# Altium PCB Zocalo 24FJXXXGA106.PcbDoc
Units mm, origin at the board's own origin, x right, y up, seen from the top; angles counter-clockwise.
Board outline 80.82 x 80.01 mm, 2 copper layers (TopLayer, BottomLayer); 8 components, 106 nets, 200 pads, 93 vias.
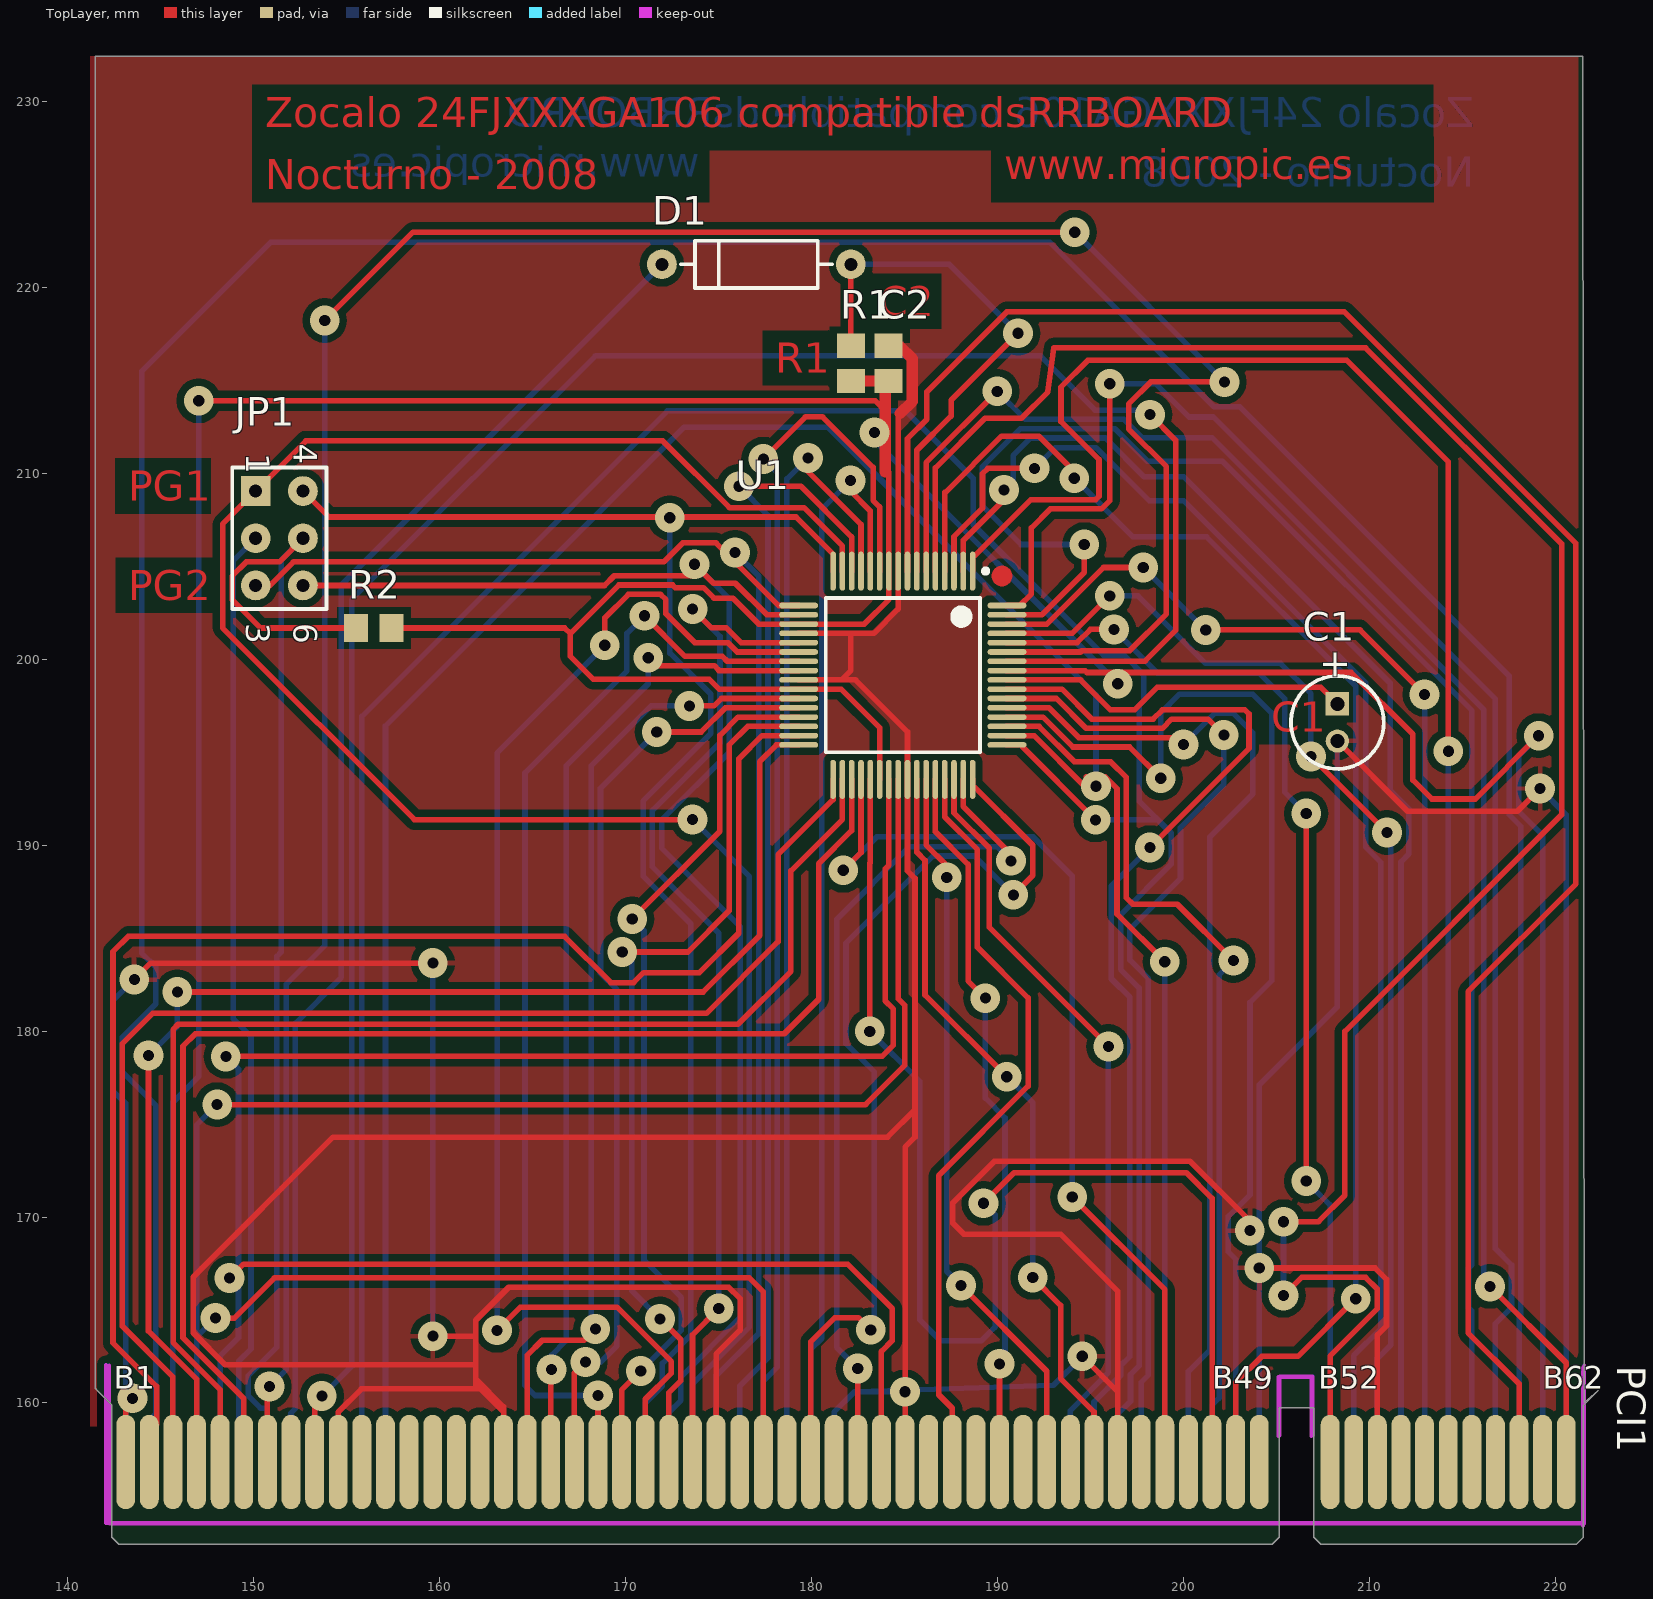
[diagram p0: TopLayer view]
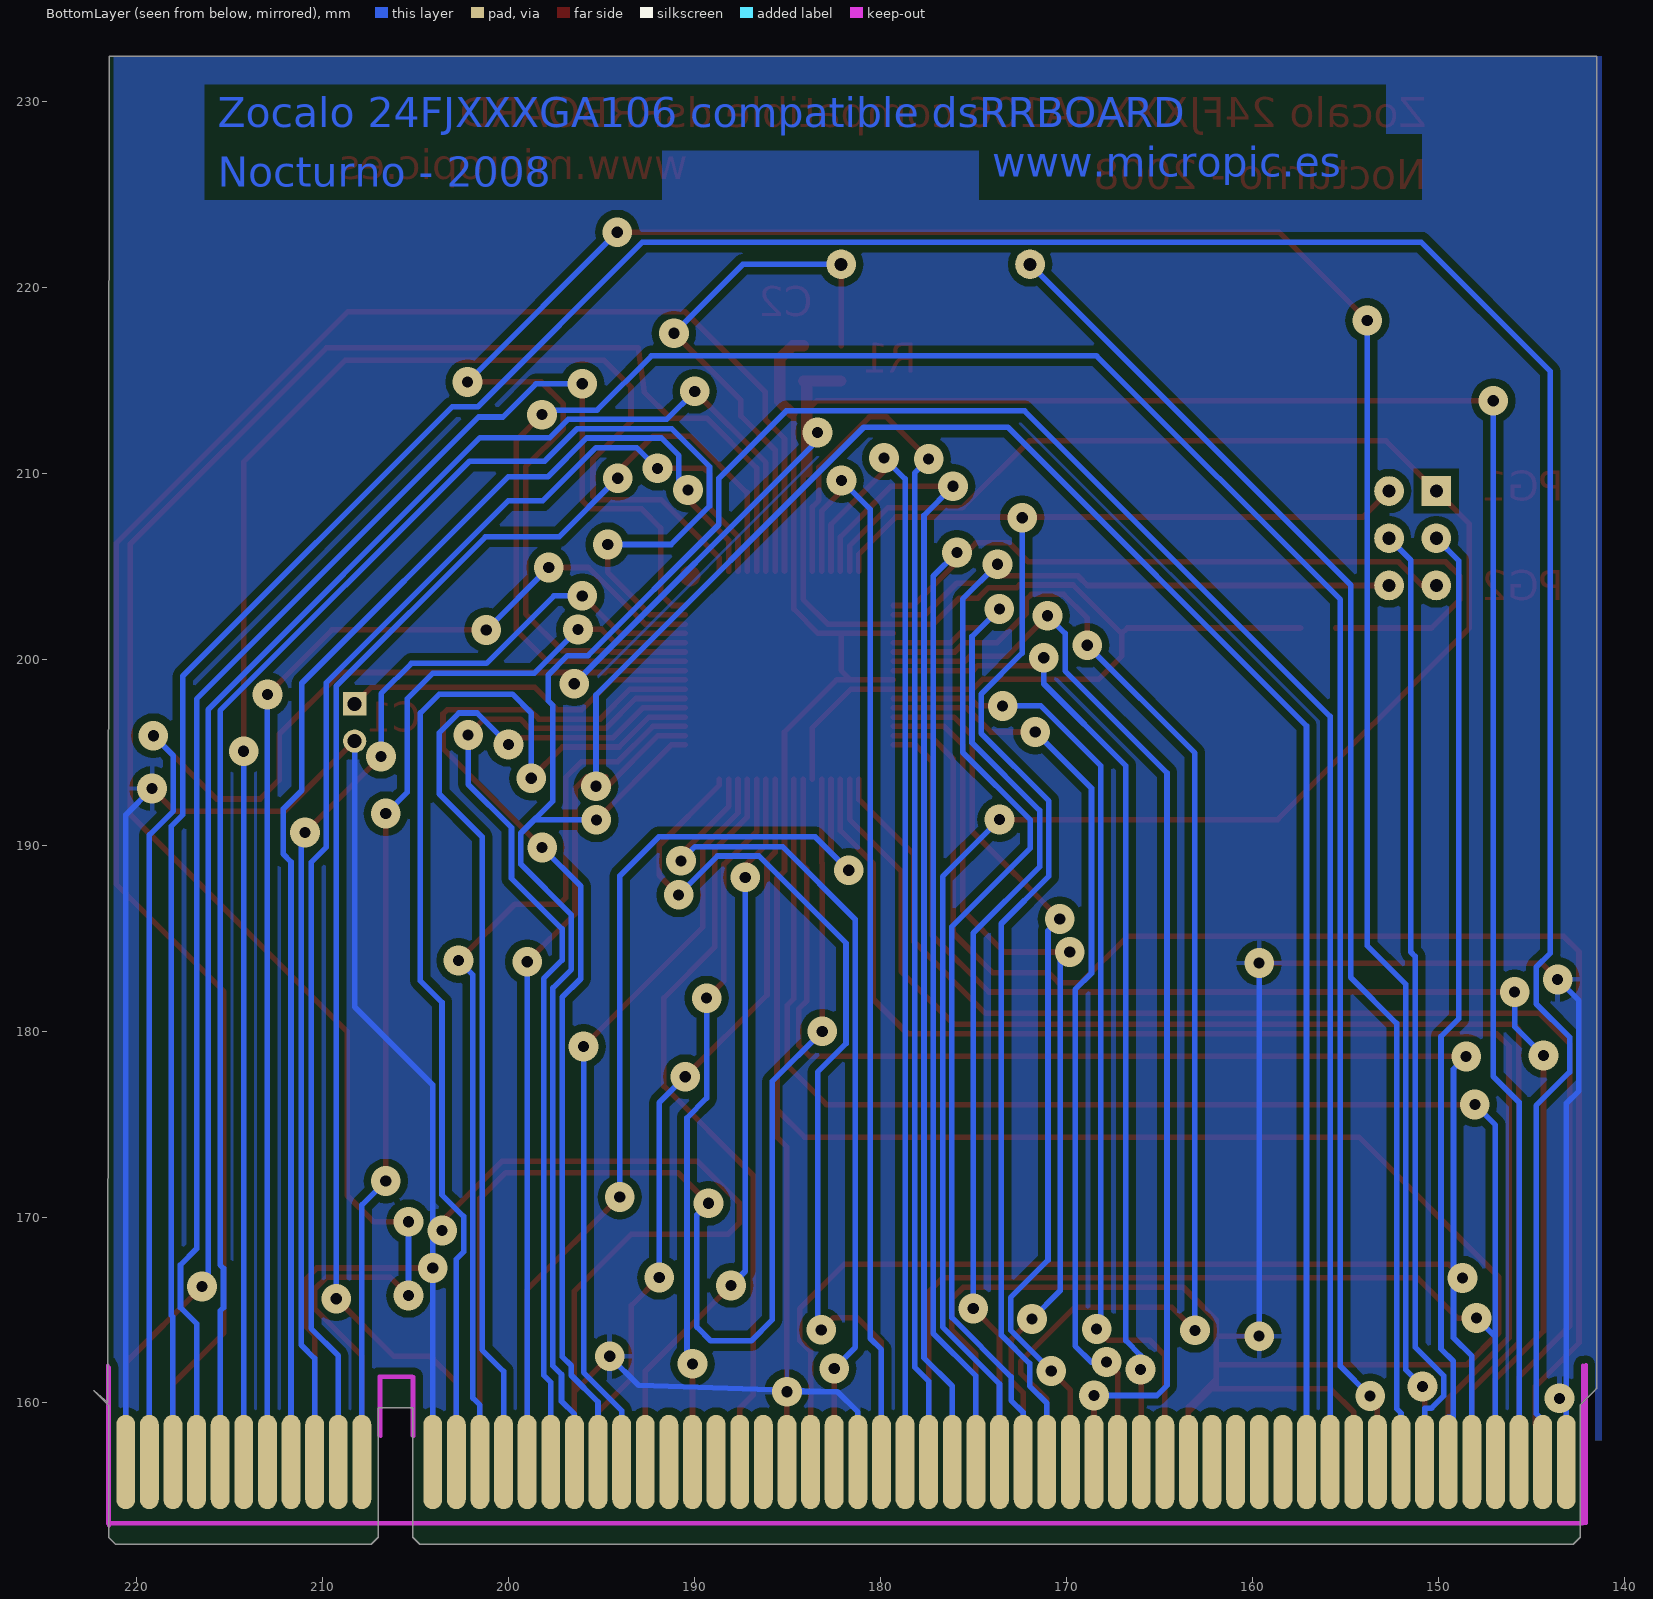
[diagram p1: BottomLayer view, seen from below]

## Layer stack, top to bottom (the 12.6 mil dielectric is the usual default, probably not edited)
TopLayer: signal copper 0.0356
Dielectric: core 0.32, FR-4, Dk 4.8
BottomLayer: signal copper 0.0356

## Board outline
141.478,160.782 142.367,159.893 142.367,152.781 142.748,152.4 204.775,152.4 205.156,152.781 205.156,159.741 207.01,159.741 207.01,152.781 207.391,152.4 221.132,152.4 221.513,152.781 221.513,159.868 222.301,160.655 221.553,160.02 221.488,232.41 141.478,232.41

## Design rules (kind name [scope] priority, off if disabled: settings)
Clearance [All] p1: gap=0.2
ComponentClearance [All] p1: gap=0.254 collisioncheckmode=0 verticalgap=0.254
PasteMaskExpansion PasteMaskExpansion_1 [InComponent('P1')] p1: expansion=-2.54
PasteMaskExpansion [All] p2: expansion=0
PlaneClearance [All] p1: clearance=0.254
PolygonConnect [All] p1: connectstyle=Relief reliefconductorwidth=0.254 reliefentries=4 polygonreliefangle="90 Angle"
RoutingVias [All] p1: holewidth=0.6 width=1.6 viastyle="Through Hole" minholewidth=0.6 minwidth=1.6 maxholewidth=0.6 maxwidth=1.6
SolderMaskExpansion [All] p1: expansion=0.051
TestPointUsage [All] p1: valid=0 allowmultiple=FALSE
Testpoint [All] p1: side=7 testpointundercomponent=TRUE minsize=1.016 maxsize=2.54 preferedsize=1.524 minholesize=0.508 maxholesize=1.016 preferedholesize=0.813 testpointgrid=0.025 style=1001 order=0123456789
Width [All] p1: maxlimit=0.6 minlimit=0.254 preferedwidth=0.4 toplayer_prefwidth=0.3 bottomlayer_prefwidth=0.3 minimp=50.000000 maximp=50.000000 favimp=50.000000
16 further rules are at their usual default settings.

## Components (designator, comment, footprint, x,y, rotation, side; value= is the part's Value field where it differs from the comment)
C1 "10uF" B 208.28,196.596 r270 top
C2 "100nF" 2012[0805] 184.15,215.9 r270 top
D1 "BAT85" DIODE-0.4 177.038,221.234 r180 top
JP1 "Header 3X2A" HDR2X3_CEN 150.114,209.042 r270 top
PCI1 "Conector PCI Macho" PCI_MACHO 170.688,162.052 r0 top
R1 "Res1" 2012[0805] 182.118,215.9 r270 top
R2 "220" 2012[0805] 156.464,201.676 r0 top
U1 "24FJXXXGA106" TQFP64_M 184.912,199.136 r270 top

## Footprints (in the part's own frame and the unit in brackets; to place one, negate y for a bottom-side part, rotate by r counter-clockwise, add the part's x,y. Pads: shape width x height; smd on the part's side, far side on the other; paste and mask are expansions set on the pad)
2012[0805] [mm] "Chip Resistor; Body 2.0 x 1.3 mm (LxW typ)"
  rect 1.3x1.5 smd: 1(-0.95,0) 2(0.95,0)
B [mm] "Capacitor, Electrolytic, Radial; Body 5 x 6.8 mm (Dia.xH typ); Pin Spacing 2 mm (typ)"
  rect 1.25x1.25 hole 0.75: 1(-1,0)
  round 1.25 hole 0.75: 2(1,0)
  silkscreen extent -2.5,-2.5 2.5,2.5
DIODE-0.4 [mm] "Tunnel Diode - Dependent Source Model; 2 Leads"
  round 1.6 hole 0.7: 1(-5.08,0) 2(5.08,0)
  silkscreen extent -4.06,-1.27 4.06,1.27
HDR2X3_CEN [mm] "Connector; Header; 3x2 Position"
  rect 1.6x1.6 hole 0.7: 1(0,0)
  round 1.6 hole 0.7: 2(2.54,0) 3(5.08,0) 4(0,2.54) 5(2.54,2.54) 6(5.08,2.54)
  silkscreen extent -1.27,-1.27 6.35,3.81
PCI_MACHO [mil] "Conector PCI Macho"
  oval 40x200 smd far side: A1(-1085.31,-205.75) A2(-1035.31,-205.75) A3(-985.31,-205.75) A4(-935.31,-205.75) A5(-885.31,-205.75) A6(-835.31,-205.75) A7(-785.31,-205.75) A8(-735.31,-205.75) A9(-685.31,-205.75) A10(-635.31,-205.75) A11(-585.31,-205.75) A12(-535.31,-205.75) A13(-485.31,-205.75) A14(-435.31,-205.75) A15(-385.31,-205.75) A16(-335.31,-205.75) A17(-285.31,-205.75) A18(-235.31,-205.75) A19(-185.31,-205.75) A20(-135.31,-205.75) A21(-85.31,-205.75) A22(-35.31,-205.75) A23(14.69,-205.75) A24(64.69,-205.75) A25(114.69,-205.75) A26(164.69,-205.75) A27(214.69,-205.75) A28(264.69,-205.75) A29(314.69,-205.75) A30(364.69,-205.75) A31(414.69,-205.75) A32(464.69,-205.75) A33(514.69,-205.75) A34(564.69,-205.75) A35(614.69,-205.75) A36(664.69,-205.75) A37(714.69,-205.75) A38(764.69,-205.75) A39(814.69,-205.75) A40(864.69,-205.75) A41(914.69,-205.75) A42(964.69,-205.75) A43(1014.69,-205.75) A44(1064.69,-205.75) A45(1114.69,-205.75) A46(1164.69,-205.75) A47(1214.69,-205.75) A48(1264.69,-205.75) A49(1314.69,-205.75) A50(1464.69,-205.75) A51(1514.69,-205.75) A52(1564.69,-205.75) A53(1614.69,-205.75) A54(1664.69,-205.75) A55(1714.69,-205.75) A56(1764.69,-205.75) A57(1814.69,-205.75) A58(1864.69,-205.75) A59(1914.69,-205.75) A60(1964.69,-205.75)
  oval 40x200 smd: B1(-1085.31,-205.75) B2(-1035.31,-205.75) B3(-985.31,-205.75) B4(-935.31,-205.75) B5(-885.31,-205.75) B6(-835.31,-205.75) B7(-785.31,-205.75) B8(-735.31,-205.75) B9(-685.31,-205.75) B10(-635.31,-205.75) B11(-585.31,-205.75) B12(-535.31,-205.75) B13(-485.31,-205.75) B14(-435.31,-205.75) B15(-385.31,-205.75) B16(-335.31,-205.75) B17(-285.31,-205.75) B18(-235.31,-205.75) B19(-185.31,-205.75) B20(-135.31,-205.75) B21(-85.31,-205.75) B22(-35.31,-205.75) B23(14.69,-205.75) B24(64.69,-205.75) B25(114.69,-205.75) B26(164.69,-205.75) B27(214.69,-205.75) B28(264.69,-205.75) B29(314.69,-205.75) B30(364.69,-205.75) B31(414.69,-205.75) B32(464.69,-205.75) B33(514.69,-205.75) B34(564.69,-205.75) B35(614.69,-205.75) B36(664.69,-205.75) B37(714.69,-205.75) B38(764.69,-205.75) B39(814.69,-205.75) B40(864.69,-205.75) B41(914.69,-205.75) B42(964.69,-205.75) B43(1014.69,-205.75) B44(1064.69,-205.75) B45(1114.69,-205.75) B46(1164.69,-205.75) B47(1214.69,-205.75) B48(1264.69,-205.75) B49(1314.69,-205.75) B50(1464.69,-205.75) B51(1514.69,-205.75) B52(1564.69,-205.75) B53(1614.69,-205.75) B54(1664.69,-205.75) B55(1714.69,-205.75) B56(1764.69,-205.75) B57(1814.69,-205.75) B58(1864.69,-205.75) B59(1914.69,-205.75) B60(1964.69,-205.75)
  KeepOutLayer lines w8: -1120.31,-0.75 -1120.31,-335.75 1998.63,-335.75 ; 1354.69,-150.75 1354.69,-25.75 1424.69,-25.75 1424.69,-150.75 ; 2002.57,-335.75 2002.57,-0.75
TQFP64_M [mm] "Thin QFP, 64-Leads, Body 10x10mm, Pitch 0.5mm, IPC Low Density"
  oval 2.1x0.3 smd: 1(-5.6,3.75) 2(-5.6,3.25) 3(-5.6,2.75) 4(-5.6,2.25) 5(-5.6,1.75) 6(-5.6,1.25) 7(-5.6,0.75) 8(-5.6,0.25) 9(-5.6,-0.25) 10(-5.6,-0.75) 11(-5.6,-1.25) 12(-5.6,-1.75) 13(-5.6,-2.25) 14(-5.6,-2.75) 15(-5.6,-3.25) 16(-5.6,-3.75) 33(5.6,-3.75) 34(5.6,-3.25) 35(5.6,-2.75) 36(5.6,-2.25) 37(5.6,-1.75) 38(5.6,-1.25) 39(5.6,-0.75) 40(5.6,-0.25) 41(5.6,0.25) 42(5.6,0.75) 43(5.6,1.25) 44(5.6,1.75) 45(5.6,2.25) 46(5.6,2.75) 47(5.6,3.25) 48(5.6,3.75)
  oval 0.3x2.1 smd: 17(-3.75,-5.6) 18(-3.25,-5.6) 19(-2.75,-5.6) 20(-2.25,-5.6) 21(-1.75,-5.6) 22(-1.25,-5.6) 23(-0.75,-5.6) 24(-0.25,-5.6) 25(0.25,-5.6) 26(0.75,-5.6) 27(1.25,-5.6) 28(1.75,-5.6) 29(2.25,-5.6) 30(2.75,-5.6) 31(3.25,-5.6) 32(3.75,-5.6) 49(3.75,5.6) 50(3.25,5.6) 51(2.75,5.6) 52(2.25,5.6) 53(1.75,5.6) 54(1.25,5.6) 55(0.75,5.6) 56(0.25,5.6) 57(-0.25,5.6) 58(-0.75,5.6) 59(-1.25,5.6) 60(-1.75,5.6) 61(-2.25,5.6) 62(-2.75,5.6) 63(-3.25,5.6) 64(-3.75,5.6)
  silkscreen extent -5.72,-4.15 4.15,4.58, body extent -5,-5 5,5, height 1.6

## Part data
C1: library part "Cap Pol2", "Polarized Capacitor (Axial)"
C2: library part Cap, "Capacitor"
D1: library part "Diode 1N4148", "High Conductance Fast Diode"
JP1: "Header, 3-Pin, Dual row"
R1: "Resistor"
R2: library part Res1, "Resistor"

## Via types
v1: diameter 1.6, hole 0.6, TopLayer to BottomLayer, 93 vias

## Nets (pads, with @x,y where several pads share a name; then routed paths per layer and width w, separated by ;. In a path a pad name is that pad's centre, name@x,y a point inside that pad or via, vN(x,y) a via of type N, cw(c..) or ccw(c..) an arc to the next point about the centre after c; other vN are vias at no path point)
A0: PCI1.A14
A1: PCI1.A16
A2: PCI1.A18
A3: PCI1.A20
A4: PCI1.A21
A5: PCI1.A19
A6: PCI1.A17
A7: PCI1.A15
A9: PCI1.B15
A10: PCI1.B13
A12: PCI1.B11
A13: PCI1.B12
A14: PCI1.B14
A15: PCI1.B16
B0: JP1.4 PCI1.A23 U1.16 | length 86.1
  TopLayer w0.3: JP1.4 154.05,207.646 179.166,207.646 181.162,205.65 U1.16 ; v1(172.381,207.603) v1@172.381,207.646
  BottomLayer w0.3: PCI1.A23 171.061,159.998 171.982,160.919 171.982,162.128 173.506,163.652 173.506,185.769 170.943,188.332 170.943,192.373 174.581,196.011 174.581,198.12 172.381,200.321 v1(172.381,207.603)
B1: JP1.1 PCI1.A25 U1.15 | length 111.1
  TopLayer w0.3: v1(173.601,191.371) 158.641,191.371 148.336,201.676 148.336,207.264 152.806,211.734 172.002,211.734 175.59,208.146 179.592,208.146 181.662,206.076 U1.15
  BottomLayer w0.3: PCI1.A25 173.601,161.022 176.663,164.084 176.663,188.309 v1(173.601,191.371)
B2: PCI1.A27 U1.14 | length 62.8
  TopLayer w0.3: v1(176.098,209.296) 179.436,209.296 182.162,206.57 U1.14
  BottomLayer w0.3: v1(176.098,209.296) 177.663,207.731 177.663,162.425 176.141,160.903 PCI1.A27
B3: PCI1.A29 U1.13 | length 61.7
  TopLayer w0.3: v1(179.807,210.82) 179.807,210.097 182.662,207.242 U1.13
  BottomLayer w0.3: PCI1.A29 178.681,209.695 v1(179.807,210.82)
B4: PCI1.A30 U1.12 | length 59.4
  TopLayer w0.3: v1@182.366,209.327 v1(182.093,209.601) 182.093,209.046 183.162,207.977 U1.12
  BottomLayer w0.3: PCI1.A30 179.951,162.868 180.562,163.479 180.562,208.07 v1(182.093,209.601)
B5: PCI1.A28 U1.11 | length 68.2
  TopLayer w0.3: v1(177.411,210.761) 179.68,213.03 180.594,213.03 183.312,210.312 183.312,208.534 183.662,208.184 U1.11
  BottomLayer w0.3: PCI1.A28 177.411,161.173 178.163,161.924 178.163,210.009 v1(177.411,210.761)
B6: JP1.3 PCI1.A26 U1.17 | length 82.4
  TopLayer w0.3: JP1.3 150.876,203.962 152.146,205.232 172.053,205.232 173.076,206.255 174.864,206.255 178.233,202.886 U1.17 ; v1@175.887,205.232 v1(175.887,205.74)
  BottomLayer w0.3: PCI1.A26 174.871,161.453 177.163,163.745 177.163,204.464 v1(175.887,205.74)
B7: JP1.6 PCI1.A24 U1.18 | length 82.5
  TopLayer w0.3: JP1.6 168.868,203.962 169.393,204.486 173.711,204.486 v1(173.711,205.105) 174.734,204.082 175.902,204.082 177.598,202.386 U1.18
  BottomLayer w0.3: PCI1.A24 172.331,159.5 172.973,160.142 172.973,161.402 176.163,164.592 176.163,185.62 171.943,189.84 171.943,191.357 175.581,194.995 175.581,203.234 v1(173.711,205.105)
B8/H0: PCI1.B25 U1.21 | length 56.5
  TopLayer w0.3: PCI1.B25 173.601,163.663 v1(175.013,165.075) ; v1(173.609,202.698) 174.625,201.682 175.421,201.682 176.217,200.886 U1.21
  BottomLayer w0.3: v1(173.609,202.698) 175.081,201.226 175.081,195.503 171.443,191.865 171.443,188.832 175.013,185.263 v1(175.013,165.075)
B9/H1: PCI1.B23 U1.22 | length 70.5
  TopLayer w0.3: v1(163.093,163.906) 164.342,165.154 169.533,165.154 172.466,162.222 172.466,161.603 171.061,160.198 PCI1.B23 ; v1(168.884,200.744) 168.884,202.215 170.155,203.486 171.882,203.486 172.168,203.2 172.168,202.441 173.727,200.882 175.514,200.882 176.01,200.386 U1.22
  BottomLayer w0.3: v1(163.093,163.906) 163.093,194.954 v1(168.884,200.744)
B10/H2: PCI1.B21 U1.23 | length 61.1
  TopLayer w0.3: PCI1.B21 v1(168.521,160.401) ; v1(171.018,202.336) 173.203,200.151 175.204,200.151 175.469,199.886 U1.23
  BottomLayer w0.3: v1(168.521,160.401) 165.141,160.401 164.592,160.95 164.592,193.887 170.071,199.367 170.071,201.39 v1(171.018,202.336)
B11/H3: PCI1.B19 U1.24 | length 53.8
  TopLayer w0.3: PCI1.B19 165.981,161.765 v1(166.014,161.798) ; v1(171.221,200.076) 171.646,199.651 174.777,199.651 175.006,199.423 175.006,199.386 U1.24
  BottomLayer w0.3: v1(166.014,161.798) 166.014,162.564 166.802,163.351 166.802,194.259 171.221,198.679 v1(171.221,200.076)
B12/H4: PCI1.B18 U1.27 | length 53
  TopLayer w0.3: PCI1.B18 164.711,162.56 165.524,163.373 167.767,163.373 v1(168.377,163.982) ; v1(173.431,197.485) 174.758,197.485 175.159,197.886 U1.27
  BottomLayer w0.3: v1(168.377,163.982) 168.148,164.211 168.148,194.259 171.374,197.485 v1(173.431,197.485)
B13/H5: PCI1.B20 U1.28 | length 50.5
  TopLayer w0.3: PCI1.B20 167.251,161.612 v1(167.843,162.204) ; v1(171.681,196.082) 174.063,196.082 175.367,197.386 U1.28
  BottomLayer w0.3: v1(167.843,162.204) 168.67,162.204 169.533,163.068 169.533,182.231 168.656,183.109 168.656,193.057 v1(171.681,196.082)
B14/H6: PCI1.B22 U1.29 | length 48.1
  TopLayer w0.3: PCI1.B22 169.791,160.698 v1(170.815,161.722) ; v1(170.358,186.03) 175.075,190.746 175.075,195.903 176.058,196.886 U1.29
  BottomLayer w0.3: v1(170.358,186.03) 170.993,185.395 170.993,167.679 173.006,165.666 173.006,163.913 v1(170.815,161.722)
B15/H7: PCI1.B24 U1.30 | length 48.7
  TopLayer w0.3: v1(169.824,184.252) 173.356,184.252 175.575,186.471 175.575,195.387 176.574,196.386 U1.30 ; v1(171.856,164.516) 172.973,163.399 172.973,161.2 172.331,160.558 PCI1.B24
  BottomLayer w0.3: v1(169.824,184.252) 170.332,183.744 170.332,166.04 v1(171.856,164.516)
C0: PCI1.A32
C1: PCI1.A34
C2: PCI1.A36
C3: PCI1.A38
C4: PCI1.A39
C5: PCI1.A37
C6: PCI1.A35
C7: PCI1.A33
C12: PCI1.A5 PCI1.B33 U1.39 | length 119.3
  TopLayer w0.3: v1(148.506,178.638) 183.794,178.638 184.404,179.248 184.404,181.178 183.966,181.616 183.966,188.722 184.162,188.918 U1.39 ; v1(148.709,166.717) 149.462,167.469 181.942,167.469 184.342,165.069 184.342,163.35 183.761,162.769 PCI1.B33
  BottomLayer w0.3: PCI1.A5 148.201,162.521 149.188,163.508 149.188,177.956 v1(148.506,178.638) ; v1(148.709,166.717) v1@149.188,166.238
C13: PCI1.B32 U1.47 | length 46.9
  TopLayer w0.3: PCI1.B32 v1(182.491,161.857) ; U1.47 188.162,192.076 190.729,189.509 v1(190.729,189.154) v1@190.366,189.516
  BottomLayer w0.3: v1(182.491,161.857) 181.357,162.991 181.357,186.005 185.267,189.915 189.968,189.915 v1(190.729,189.154)
C14: PCI1.B30 U1.48 | length 51.8
  TopLayer w0.3: PCI1.B30 179.951,163.289 181.254,164.592 182.524,164.592 v1(183.185,163.932) ; U1.48 188.662,193.227 191.897,189.992 191.897,188.366 v1(190.856,187.325)
  BottomLayer w0.3: v1(183.185,163.932) 183.381,164.128 183.381,177.8 181.857,179.324 181.857,184.727 186.545,189.415 188.766,189.415 v1(190.856,187.325)
C15: PCI1.A4 PCI1.B28 U1.40 | length 114.3
  TopLayer w0.3: v1(147.947,164.567) 148.963,164.567 151.121,166.725 176.663,166.725 177.411,165.977 PCI1.B28 ; v1(148.038,176.047) 182.905,176.047 185.011,178.154 185.011,181.397 184.662,181.746 U1.40
  BottomLayer w0.3: PCI1.A4 146.931,174.94 v1(148.038,176.047) ; 146.931,163.551 v1(147.947,164.567)
D0: PCI1.A41 U1.46 | length 40.9
  TopLayer w0.3: U1.46 187.662,191.734 189.566,189.83 ; 189.566,189.738 189.566,185.572 v1(195.968,179.17)
  BottomLayer w0.3: PCI1.A41 193.921,159.592 195.968,161.639 v1(195.968,179.17)
D1: PCI1.A11 PCI1.A43 U1.49 | length 151.2
  TopLayer w0.3: U1.49 191.253,195.386 v1(195.281,191.358)
  BottomLayer w0.3: PCI1.A11 155.821,196.918 172.251,213.349 185.072,213.349 188.698,209.723 188.698,207.226 195.731,200.193 196.823,200.193 197.879,199.136 197.879,197.773 197.618,197.512 197.618,192.368 199.346,190.64 199.346,188.976 196.622,186.252 196.622,183.313 197.618,182.317 197.618,161.995 197.154,161.531 197.154,160.095 196.461,159.402 PCI1.A43 ; v1(195.281,191.358) 198.628,191.358
D2: PCI1.A12 PCI1.A45 U1.50 | length 141.5
  TopLayer w0.3: U1.50 191.972,195.886 194.664,193.194 v1@195.301,193.194 ; v1(195.301,193.167) v1@195.301,193.194 ; v1(199.001,183.726) 196.431,186.296 196.431,193.04 195.789,193.682 v1@195.301,193.194 ; v1@195.301,193.194 194.786,193.682 v1@195.301,193.194
  BottomLayer w0.3: PCI1.A12 157.091,196.41 173.152,212.471 180.903,212.471 195.301,198.074 v1(195.301,193.167) ; PCI1.A45 v1(199.001,183.726)
D3: PCI1.A47 U1.51 | length 48.6
  TopLayer w0.3: U1.51 192.238,196.386 194.142,194.482 196.088,194.482 196.931,193.639 196.931,187.166 197.28,186.817 199.669,186.817 v1(202.692,183.794)
  BottomLayer w0.3: PCI1.A47 201.541,159.885 201.923,160.267 201.923,183.026 v1(202.692,183.794)
D4: PCI1.A48 U1.52 | length 61.3
  TopLayer w0.3: U1.52 192.445,196.886 194.056,195.275 197.105,195.275 v1(198.78,193.599)
  BottomLayer w0.3: v1(198.78,193.599) 198.78,197.104 199.796,198.12 203.727,198.12 204.743,197.104 204.743,182.703 203.581,181.541 203.581,171.193 202.423,170.035 202.423,168.123 202.811,167.735 PCI1.A48
D5: PCI1.A46 U1.53 | length 55.8
  TopLayer w0.3: U1.53 192.769,197.386 194.38,195.775 199.652,195.775 v1(200.012,195.415)
  BottomLayer w0.3: v1(200.012,195.415) 201.701,197.104 202.667,197.104 203.733,196.037 203.733,192.761 201.423,190.45 201.423,162.848 200.271,161.696 PCI1.A46
D6: PCI1.A44 U1.54 | length 54.6
  TopLayer w0.3: U1.54 193.166,197.886 194.778,196.275 198.873,196.275 199.371,196.773 201.321,196.773 v1(202.175,195.919)
  BottomLayer w0.3: PCI1.A44 197.731,161.108 198.118,161.495 198.118,182.817 197.122,183.813 197.122,185.491 199.846,188.215 199.846,190.944 202.175,193.272 v1(202.175,195.919)
D7: PCI1.A42 U1.55 | length 58.5
  TopLayer w0.3: U1.55 193.462,198.386 195.073,196.775 198.373,196.775 198.871,197.273 203.31,197.273 203.53,197.053 203.53,195.199 v1(198.196,189.865)
  BottomLayer w0.3: PCI1.A42 195.191,160.054 196.63,161.493 196.63,162.007 197.118,162.495 197.118,181.817 196.122,182.813 196.122,187.791 v1(198.196,189.865)
D8/J0: PCI1.B42 U1.42 | length 40.7
  TopLayer w0.3: U1.42 185.662,189.623 186.106,189.179 186.106,181.94 v1(190.5,177.546) ; v1(191.897,166.751) 193.396,165.252 193.396,161.315 195.191,159.52 PCI1.B42
  BottomLayer w0.3: v1(190.5,177.546) 191.897,176.149 v1(191.897,166.751)
D9/J1: PCI1.B40 U1.43 | length 39.6
  TopLayer w0.3: U1.43 186.162,190.012 187.274,188.9 v1(187.274,188.265) v1@187.166,188.373 ; v1(188.036,166.319) 192.651,161.704 PCI1.B40
  BottomLayer w0.3: v1(187.274,188.265) 187.274,167.081 v1(188.036,166.319)
D10/J2: PCI1.B38 U1.44 | length 38.4
  TopLayer w0.3: U1.44 186.662,190.719 188.424,188.957 188.424,182.695 v1(189.349,181.77) ; PCI1.B38 v1(190.111,162.103)
  BottomLayer w0.3: v1(189.349,181.77) 189.349,176.39 190.405,175.333 190.405,162.397 v1(190.111,162.103)
D11/J3: PCI1.B36 U1.45 | length 40.9
  TopLayer w0.3: U1.45 187.162,191.527 188.925,189.763 188.925,184.506 191.65,181.781 191.65,177.038 186.842,172.23 186.842,160.444 187.571,159.715 PCI1.B36
D12/J4: PCI1.B35
D13/J5: PCI1.B37
D14/J6: PCI1.B39
D15/J7: PCI1.B41
D+: PCI1.A9
D-: PCI1.A10
E0: PCI1.A50 U1.60 | length 59
  TopLayer w0.3: U1.60 194.287,200.886 195.001,201.6 v1(196.266,201.6) v1@196.184,201.682 ; v1(206.604,171.933) v1(206.604,191.694)
  BottomLayer w0.3: v1(196.266,201.6) 198.628,199.238 204.089,199.238 205.461,197.866 205.461,192.837 v1(206.604,191.694) ; v1(206.604,171.933) 207.891,170.645 PCI1.A50
E1: PCI1.A52 U1.61 | length 62.8
  TopLayer w0.3: U1.61 194.02,201.386 v1(196.037,203.403) ; v1(206.858,194.767) v1(210.947,190.678)
  BottomLayer w0.3: v1(196.037,203.403) 197.561,203.403 201.193,199.771 205.232,199.771 206.858,198.145 v1(206.858,194.767) ; PCI1.A52 210.431,162.4 211.15,163.119 211.15,190.475 v1(210.947,190.678)
E2: PCI1.A54 U1.62 | length 67.8
  TopLayer w0.3: U1.62 192.66,201.886 195.705,204.931 v1(197.842,204.931) ; v1(201.198,201.574) 209.499,201.574 v1(212.971,198.102)
  BottomLayer w0.3: v1(197.842,204.931) v1(201.198,201.574) ; PCI1.A54 v1(212.971,198.102)
E3: PCI1.A56 U1.63 | length 89
  TopLayer w0.3: U1.63 192.385,202.386 194.671,204.672 v1(194.671,206.165)
  BottomLayer w0.3: v1(194.671,206.165) 191.262,206.165 189.198,208.229 189.198,210.355 191.237,212.394 196.308,212.394 198.06,210.641 202.098,210.641 215.511,197.228 215.511,167.418 215.334,167.241 215.334,165.129 215.511,164.952 PCI1.A56
E4: PCI1.A57 U1.64 | length 85.7
  TopLayer w0.3: U1.64 191.202,202.886 191.821,203.505 191.821,207.061 192.838,208.078 195.596,208.078 196.043,208.525 v1(196.043,214.807)
  BottomLayer w0.3: v1(196.043,214.807) 198.526,214.807 200.309,213.024 201.616,213.024 216.781,197.859 216.781,168.294 217.645,167.429 217.645,165.129 216.781,164.265 PCI1.A57
E5: PCI1.A55 U1.1 | length 93.1
  TopLayer w0.3: U1.1 188.662,205.446 191.794,208.578 195.283,208.578 195.46,208.754 195.46,210.737 193.42,212.777 193.42,214.629 194.857,216.066 208.795,216.066 214.249,210.612 v1(214.249,195.047)
  BottomLayer w0.3: PCI1.A55 214.241,195.039 v1(214.249,195.047)
E6: PCI1.A53 U1.2 | length 75.9
  TopLayer w0.3: U1.2 188.162,206.385 190.348,208.571 v1(190.348,209.093) v1@190.366,209.074
  BottomLayer w0.3: v1(190.348,209.093) 190.842,209.587 190.842,210.947 191.788,211.894 195.808,211.894 197.897,209.804 200.025,209.804 211.125,198.704 211.125,192.946 212.12,191.951 212.12,189.521 211.701,189.102 PCI1.A53
E7: PCI1.A51 U1.3 | length 75.1
  TopLayer w0.3: U1.3 187.662,206.592 189.198,208.128 189.198,209.975 189.484,210.261 v1(191.999,210.261)
  BottomLayer w0.3: v1(191.999,210.261) 193.116,211.379 195.301,211.379 198.171,208.509 200.025,208.509 209.797,198.737 209.797,189.891 210.617,189.071 210.617,164.008 209.161,162.552 PCI1.A51
E8: PCI1.B27
E9: PCI1.B29
F0: PCI1.B9 U1.58 | length 118.7
  TopLayer w0.3: PCI1.B9 153.281,159.987 v1(153.67,160.376) ; U1.58 194.648,199.886 ; 194.764,199.898 197.937,199.898 199.584,201.545 199.584,211.772 v1(198.207,213.149)
  BottomLayer w0.3: v1(153.67,160.376) 155.27,161.976 155.27,203.2 168.384,216.313 192.326,216.313 195.245,213.394 197.962,213.394 v1(198.207,213.149)
F1: PCI1.B7 U1.59 | length 143.5
  TopLayer w0.3: PCI1.B7 150.741,160.774 v1(150.851,160.884) ; v1(153.822,218.211) 158.572,222.961 v1(194.158,222.961) ; U1.59 194.468,200.386 194.532,200.45 197.104,200.45 199.084,202.43 199.084,210.355 197.053,212.386 197.053,213.716 198.247,214.909 v1(202.209,214.909)
  BottomLayer w0.3: v1(150.851,160.884) 151.748,161.781 151.748,182.508 153.822,184.582 v1(153.822,218.211) ; v1(194.158,222.961) v1(202.209,214.909)
F2: PCI1.B5 U1.34 | length 70.3
  TopLayer w0.3: PCI1.B5 148.201,160.718 145.669,163.25 145.669,180.086 145.948,180.365 176.047,180.365 178.892,183.21 178.892,188.613 181.662,191.383 U1.34
F3: PCI1.B3 U1.33 | length 71.1
  TopLayer w0.3: PCI1.B3 145.661,161.407 142.944,164.124 142.944,179.324 144.57,180.95 174.346,180.95 178.206,184.81 178.206,189.49 181.162,192.445 U1.33
F4: PCI1.B2 U1.31 | length 78
  TopLayer w0.3: PCI1.B2 144.391,158.852 144.78,158.852 144.78,160.891 142.436,163.234 142.436,184.27 143.256,185.09 166.726,185.09 169.214,182.602 170.435,182.602 170.977,183.143 173.975,183.143 176.091,185.26 176.091,194.633 177.344,195.886 U1.31
F5: PCI1.B4 U1.32 | length 71.4
  TopLayer w0.3: v1(144.348,178.689) 144.348,163.864 146.931,161.281 PCI1.B4 ; v1(145.898,182.102) 174.177,182.102 177.216,185.141 177.216,194.488 178.114,195.386 U1.32
  BottomLayer w0.3: v1(144.348,178.689) 145.898,180.238 v1(145.898,182.102)
F6: PCI1.B6 U1.35 | length 71.5
  TopLayer w0.3: PCI1.B6 149.471,160.24 146.202,163.509 146.202,179.193 146.866,179.857 178.536,179.857 180.391,181.712 180.391,189.007 182.162,190.778 U1.35
F7: PCI1.B8
F8: PCI1.B31
G0: PCI1.B51
G1: PCI1.B49
G2: PCI1.B47 U1.37 | length 69.6
  TopLayer w0.3: v1(183.134,179.984) 183.134,189.021 183.162,189.049 U1.37 ; v1(189.255,170.739) 190.906,172.39 200.152,172.39 201.541,171.001 PCI1.B47
  BottomLayer w0.3: v1(183.134,179.984) 185.826,177.292 185.826,164.465 186.944,163.347 189.135,163.347 189.872,164.084 189.872,170.122 v1(189.255,170.739)
G3: PCI1.B45 U1.36 | length 53
  TopLayer w0.3: v1@181.566,188.791 v1(181.712,188.646) 182.662,189.596 U1.36 ; v1(194.023,171.077) 199.001,166.098 PCI1.B45
  BottomLayer w0.3: v1(181.712,188.646) 183.516,190.451 191.921,190.451 194.023,188.349 v1(194.023,171.077)
G4: PCI1.B44
G5: PCI1.B46
G6: PCI1.B48 U1.4 | length 78.9
  TopLayer w0.3: U1.4 187.162,208.965 ; 187.198,208.965 190.223,211.989 192.22,211.989 194.133,210.076 v1(194.133,209.728) ; PCI1.B48 202.811,161.097 204.216,162.501 206.164,162.501 v1(209.271,165.608)
  BottomLayer w0.3: v1(194.133,209.728) 197.288,206.573 201.253,206.573 209.271,198.556 v1(209.271,165.608)
G7: PCI1.B50 U1.5 | length 111.1
  TopLayer w0.3: U1.5 186.662,210.284 189.332,212.954 191.287,212.954 192.71,214.376 193.04,216.738 209.804,216.738 220.345,206.197 220.345,191.643 208.686,179.984 208.686,171.171 207.264,169.748 v1(205.384,169.748) ; v1(205.384,165.786) 206.357,166.758 209.804,166.758 210.421,166.141 210.421,165.056 207.891,162.527 PCI1.B50
  BottomLayer w0.3: v1(205.384,165.786) v1(205.384,169.748)
G8: PCI1.B60 U1.6 | length 86.8
  TopLayer w0.3: U1.6 186.162,210.571 v1(189.992,214.401) ; v1(216.484,166.268) 220.591,162.161 PCI1.B60
  BottomLayer w0.3: v1(189.992,214.401) 191.5,212.894 196.8,212.894 197.781,211.912 201.534,211.912 216.154,197.292 216.154,166.599 v1(216.484,166.268)
G9: PCI1.B58 U1.8 | length 104.8
  TopLayer w0.3: U1.8 185.162,211.857 186.206,212.902 186.206,214.382 190.5,218.676 208.654,218.676 221.107,206.223 221.107,187.909 215.316,182.118 215.316,163.771 218.051,161.036 PCI1.B58
G10: PCI1.B56
G11: PCI1.B54
G12: PCI1.B53
G13: PCI1.B55
G14: PCI1.B57
G15: PCI1.B59
LED1: PCI1.A13
LED2: C1.2 C2.1 PCI1.A1 PCI1.A31 PCI1.A49 PCI1.A60 PCI1.B1 PCI1.B10 PCI1.B17 PCI1.B26 PCI1.B34 PCI1.B43 PCI1.B52 U1.9 U1.20 U1.25 U1.41 | length 417.5
  TopLayer w0.3: PCI1.B1 143.121,159.885 v1(143.485,160.249) ; v1(143.586,182.778) 144.463,183.656 v1(159.639,183.656) ; PCI1.B10 154.551,159.512 155.796,160.757 162.197,160.757 163.441,159.512 ; v1(159.639,163.594) 161.943,163.594 ; 161.943,160.757 161.943,164.447 163.721,166.225 175.546,166.225 176.163,165.608 176.163,163.925 174.871,162.633 PCI1.B26 ; 161.943,161.289 163.441,159.791 PCI1.B17 ; 161.943,162.052 148.475,162.052 146.752,163.775 146.752,166.767 154.28,174.295 184.093,174.295 185.566,175.768 ; U1.25 182.368,198.886 185.162,196.092 185.162,188.618 185.566,188.214 185.566,174.295 185.031,173.76 PCI1.B34 ; U1.20 183.352,201.386 184.662,202.696 184.662,213.214 ; 181.614,198.886 182.118,199.39 182.118,201.386 ; v1(194.564,162.509) 196.461,160.612 ; PCI1.B43 196.461,166.015 193.396,169.081 188.189,169.081 187.597,169.672 187.597,170.757 189.84,172.999 200.355,172.999 203.573,169.781 v1(203.573,169.273) ; v1(204.081,167.258) 210.312,167.258 210.921,166.649 210.921,164.143 210.431,163.653 PCI1.B52 ; C1.2 212.055,191.821 217.957,191.821 v1(219.177,193.04)
  TopLayer w0.6: C2.1 184.724,216.85 185.42,216.154 185.42,213.868 184.766,213.214
  BottomLayer w0.3: PCI1.A1 143.121,176.108 142.444,176.785 142.444,181.636 v1(143.586,182.778) ; v1@143.121,159.885 v1(143.485,160.249) ; v1(159.639,163.594) v1(159.639,183.656) ; PCI1.A31 181.221,159.512 182.313,160.604 ; v1(185.031,160.604) 182.313,160.604 ; v1(194.564,162.509) 193.008,160.953 185.028,160.693 182.313,160.604 ; v1(203.573,169.273) v1@204.081,168.765 ; PCI1.A49 204.081,177.11 208.28,181.309 C1.2 ; v1(219.177,193.04) 220.591,191.625 PCI1.A60
LED3: PCI1.A22
LED7: PCI1.A40
MCLR: D1.2 PCI1.A8 | length 72.7
  BottomLayer w0.3: PCI1.A8 152.011,159.456 152.248,159.693 152.248,180.417 154.711,182.88 154.711,203.987 D1.2
NetC1_1: C1.1 U1.56 | length 19.3
  TopLayer w0.3: U1.56 194.466,198.886 196.078,197.275 197.381,197.275 198.588,198.482 207.394,198.482 C1.1
NetD1_1: D1.1 R1.1 U1.7 | length 30
  TopLayer w0.3: R1.1 D1.1 ; U1.7 185.662,211.233 187.506,213.077 187.506,213.922 v1(191.11,217.526)
  BottomLayer w0.3: D1.1 187.401,221.234 v1(191.11,217.526)
PGC: JP1.2 PCI1.A6 | length 51.1
  BottomLayer w0.3: PCI1.A6 149.471,159.224 149.201,159.224 149.201,162.253 149.859,162.912 149.859,179.706 148.895,180.67 148.895,205.283 JP1.2
PGD: JP1.5 PCI1.A7 R2.1 | length 64.8
  TopLayer w0.3: JP1.5 151.384,205.232 149.606,205.232 148.844,204.47 148.844,203.2 150.368,201.676 R2.1
  BottomLayer w0.3: PCI1.A7 150.741,159.724 150.368,159.724 149.701,160.391 149.701,161.453 151.248,163 151.248,184.016 151.486,184.254 151.486,205.334 JP1.5
VDD3.3V: C2.2 PCI1.A3 PCI1.A59 R1.2 R2.2 U1.10 U1.19 U1.26 U1.38 U1.57 | length 258.6
  TopLayer w0.3: v1(147.048,213.893) 183.433,213.893 183.966,213.36 183.966,210.242 184.162,210.046 184.162,203.212 182.836,201.886 177.164,201.886 175.768,203.282 174.759,203.282 174.193,203.848 172.668,203.848 172.53,203.986 169.647,203.986 167.03,201.37 ; R2.2 166.725,201.676 167.03,201.37 ; v1(183.388,212.192) 183.966,211.614 ; U1.38 183.662,196.322 181.598,198.386 175.063,198.386 175.051,198.374 174.499,198.926 168.257,198.926 167.03,200.152 167.03,201.37 ; U1.57 194.714,199.386 194.818,199.282 209.023,199.282 212.344,195.961 212.344,193.497 213.36,192.481 215.7,192.481 v1(219.104,195.885) ; 195.866,199.282 v1(196.469,198.679)
  TopLayer w0.6: R1.2 183.966,214.95 183.966,210.058 ; C2.2@183.966,214.766 C2.2
  BottomLayer w0.3: PCI1.A3 145.661,176.174 147.048,177.56 v1(147.048,213.893) ; v1(183.388,212.192) 183.388,211.76 v1(196.469,198.679) ; v1(219.104,195.885) 218.027,194.807 218.027,191.839 219.321,190.545 PCI1.A59
VDD5V: PCI1.A2 PCI1.A58 | length 189.2
  BottomLayer w0.3: PCI1.A2 144.391,159.072 144.742,159.423 144.742,175.991 142.944,177.789 142.944,179.671 144.742,181.469 144.742,183.431 143.993,184.181 143.993,215.494 150.927,222.428 192.802,222.428 201.661,213.569 203.038,213.569 217.527,199.081 217.527,191.627 218.145,191.008 218.145,164.724 218.051,164.629 PCI1.A58
copper on no net: | length 1.6
  TopLayer w0.6: 190.5,204.47 ccw(c190.246,204.47) 190.5,204.47

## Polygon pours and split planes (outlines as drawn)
LED2 on TopLayer "Mechanical 1-No Net" (solid, pour order 1000): 141.224,232.41 221.234,232.41 221.234,158.496 220.98,158.75 141.224,158.75 141.224,232.41
LED2 on BottomLayer "Mechanical 1-No Net" (solid, pour order 1001): 141.224,232.41 221.234,232.41 221.234,157.988 141.224,157.988 141.224,232.41

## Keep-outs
KeepOutLayer:
  lines w0.203: 142.062,162.052 142.062,153.543 221.437,153.543 ; 205.181,158.242 205.181,161.417 206.959,161.417 206.959,158.242 ; 221.488,153.416 221.488,161.925

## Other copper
TopLayer:
  text "Zocalo 24FJXXXGA106 compatible dsRRBOARD" at 150.622,228.6 h1.6
  text "www.micropic.es" at 190.373,225.806 h1.6
  text "Nocturno - 2008" at 150.622,225.273 h1.6
  text "C2" at 183.642,218.44 h1.6
  text "R1" at 178.054,215.392 h1.6
  text "PG1" at 143.256,208.509 h1.6
  text "PG2" at 143.256,203.175 h1.6
  text "C1" at 204.724,196.088 h1.6
BottomLayer:
  text "Zocalo 24FJXXXGA106 compatible dsRRBOARD" at 215.646,228.6 h1.6
  text "www.micropic.es" at 173.99,225.933 h1.6
  text "Nocturno - 2008" at 215.646,225.4 h1.6

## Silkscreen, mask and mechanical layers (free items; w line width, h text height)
TopPaste:
  text ".GTP" at 268.656,261.696 h2.29
BottomPaste:
  text ".GBP" at 268.656,261.696 h2.29
TopSolder:
  rectangle: 141.808,151.892 222.072,159.512
  text ".GTS" at 268.656,261.696 h2.29
BottomSolder:
  rectangle: 141.808,151.892 222.072,159.512
  text ".GBS" at 268.656,261.696 h2.29
Mechanical1:
  lines w0.508: 142.367,152.781 142.748,152.4 204.775,152.4 205.156,152.781 205.156,159.741 207.01,159.741 207.01,152.781 207.391,152.4 221.132,152.4 221.513,152.781 221.513,160.655 ; 142.367,159.868 141.58,160.655 141.224,160.655 141.224,232.664 221.488,232.664 221.488,160.655
Mechanical4:
  circle w0.254: c141.698,153.526 r2.54
  lines w0.203: 298.196,185.928 302.641,185.928 302.641,178.435 ; 300.736,173.228 310.896,173.228 ; 300.736,178.308 309.626,178.308 ; 302.641,165.608 302.641,173.101 ; 304.863,164.973 312.356,164.973 ; 306.768,204.343 314.579,204.343 ; 312.483,163.068 312.483,171.958 ; 313.118,163.068 313.118,171.958 ; 314.706,198.628 314.706,206.248 ; 315.341,179.578 322.326,204.978 ; 320.738,164.973 313.245,164.973 ; 329.177,200.408 321.838,203.079 ; 302.641,173.101 303.276,169.291 302.006,169.291 302.641,173.101 ; 302.641,178.435 303.276,182.245 302.006,182.245 302.641,178.435 ; 312.356,164.973 308.546,165.608 308.546,164.338 312.356,164.973 ; 313.245,164.973 317.055,165.608 317.055,164.338 313.245,164.973 ; 314.579,204.343 310.769,204.978 310.769,203.708 314.579,204.343 ; 321.838,203.079 325.635,202.373 325.201,201.179 321.838,203.079 ; 302.133,169.418 303.149,169.418 302.641,172.847 302.133,169.418 ; 302.133,182.118 303.149,182.118 302.641,178.689 302.133,182.118 ; 302.26,169.545 303.022,169.545 302.641,172.593 302.26,169.545 ; 302.26,181.991 303.022,181.991 302.641,178.943 302.26,181.991 ; 302.387,169.672 302.641,172.339 302.895,169.672 302.387,169.672 ; 302.387,181.864 302.895,181.864 302.641,179.197 302.387,181.864 ; 302.514,169.799 302.641,172.085 302.768,169.799 302.514,169.799 ; 302.514,181.737 302.768,181.737 302.641,179.451 302.514,181.737 ; 308.673,164.465 312.102,164.973 308.673,165.481 308.673,164.465 ; 308.8,164.592 311.849,164.973 308.8,165.354 308.8,164.592 ; 308.928,164.719 311.594,164.973 308.928,165.227 308.928,164.719 ; 309.054,164.846 309.054,165.1 311.34,164.973 309.054,164.846 ; 310.896,178.308 312.483,173.228 313.118,173.228 314.706,178.308 314.706,197.675 313.753,197.675 313.753,199.898 312.166,196.088 311.849,197.675 310.896,197.675 310.896,178.308 ; 310.896,203.835 314.325,204.343 310.896,204.851 310.896,203.835 ; 311.023,203.962 314.071,204.343 311.023,204.724 311.023,203.962 ; 311.15,204.089 311.15,204.597 313.817,204.343 311.15,204.089 ; 311.277,204.216 311.277,204.47 313.563,204.343 311.277,204.216 ; 313.5,164.973 316.928,165.481 316.928,164.465 313.5,164.973 ; 313.753,164.973 316.801,165.354 316.801,164.592 313.753,164.973 ; 314.007,164.973 316.674,165.227 316.674,164.719 314.007,164.973 ; 314.262,164.973 316.548,165.1 316.548,164.846 314.262,164.973 ; 322.076,202.992 325.472,202.297 325.125,201.342 322.076,202.992 ; 322.315,202.905 325.309,202.221 325.049,201.505 322.315,202.905 ; 322.554,202.818 325.147,202.145 324.973,201.668 322.554,202.818 ; 322.792,202.732 324.984,202.069 324.897,201.83 322.792,202.732
  lines w0.254: 138.091,152.18 138.599,152.307 138.091,153.577 138.091,152.18 ; 138.096,153.572 138.642,154.858 138.125,154.94 138.096,153.572
  text "DETAIL A" at 303.276,211.328 h3.81
  text "o" at 320.421,205.296 h1.22
  text "20" at 316.293,202.755 h2.29
  text "0.071" at 288.988,184.658 h2.29
  text "+.010" at 289.306,180.848 h1.91
  text "-.015" at 289.306,177.038 h1.91
  text "0.010" at 322.326,163.703 h2.29
  text "+.005" at 322.326,159.893 h1.91
  text "-.010" at 322.326,156.083 h1.91
  text "SEE DETAIL A" at 119.126,152.4 h1.91

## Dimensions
101.092,157.226 to 141.224,160.655 on Mechanical4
